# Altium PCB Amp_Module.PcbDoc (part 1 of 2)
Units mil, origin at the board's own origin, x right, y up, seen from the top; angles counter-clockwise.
Board outline 3270 x 1420 mil, 4 copper layers (Top Layer, InternalPlane1, InternalPlane2, Bottom Layer), stack 58.358 mil thick; 81 components, 51 nets, 288 pads, 46 vias.
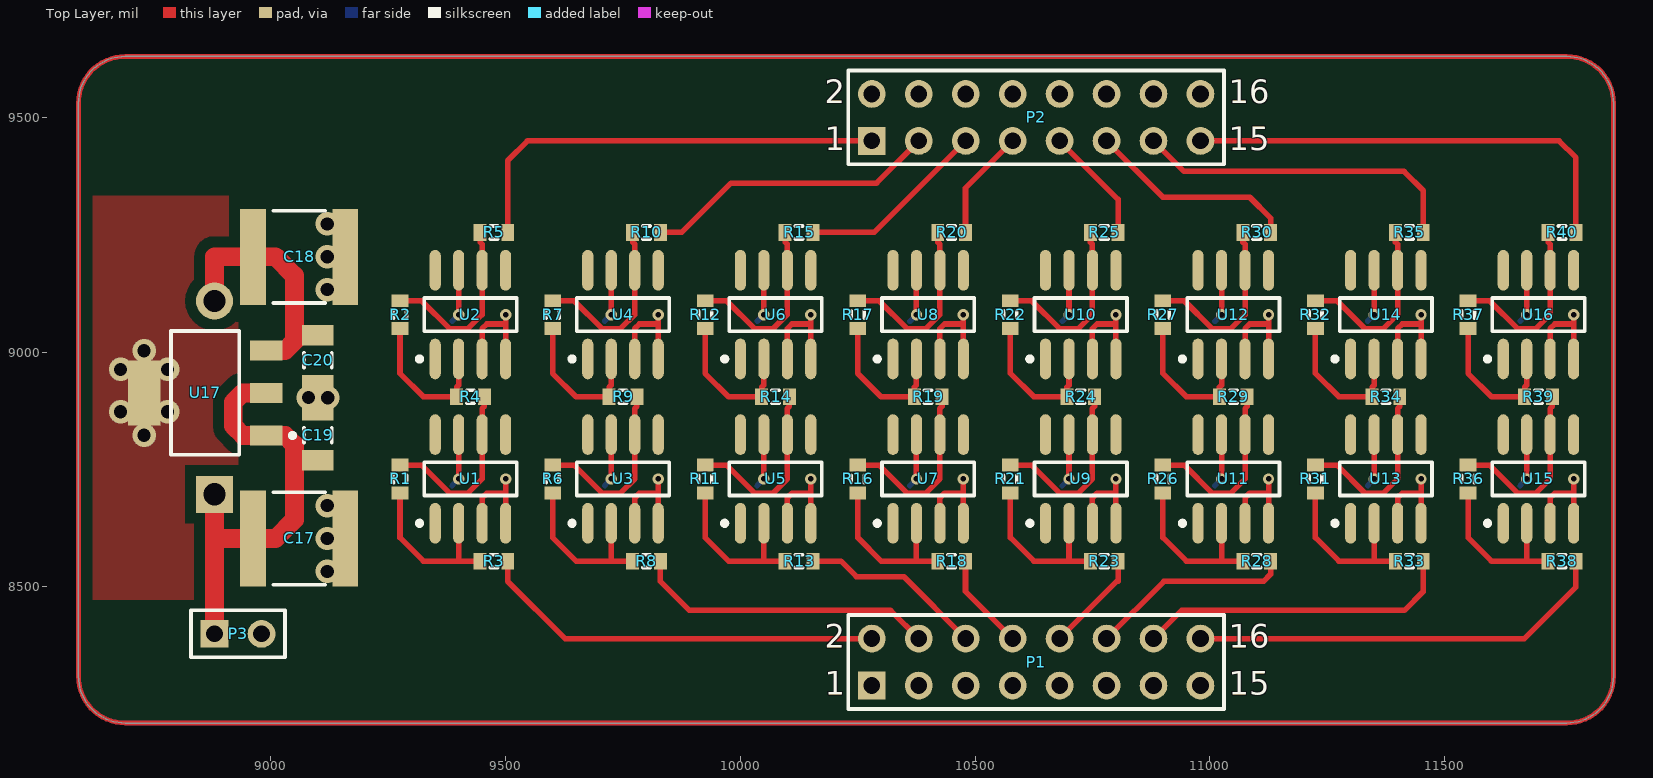
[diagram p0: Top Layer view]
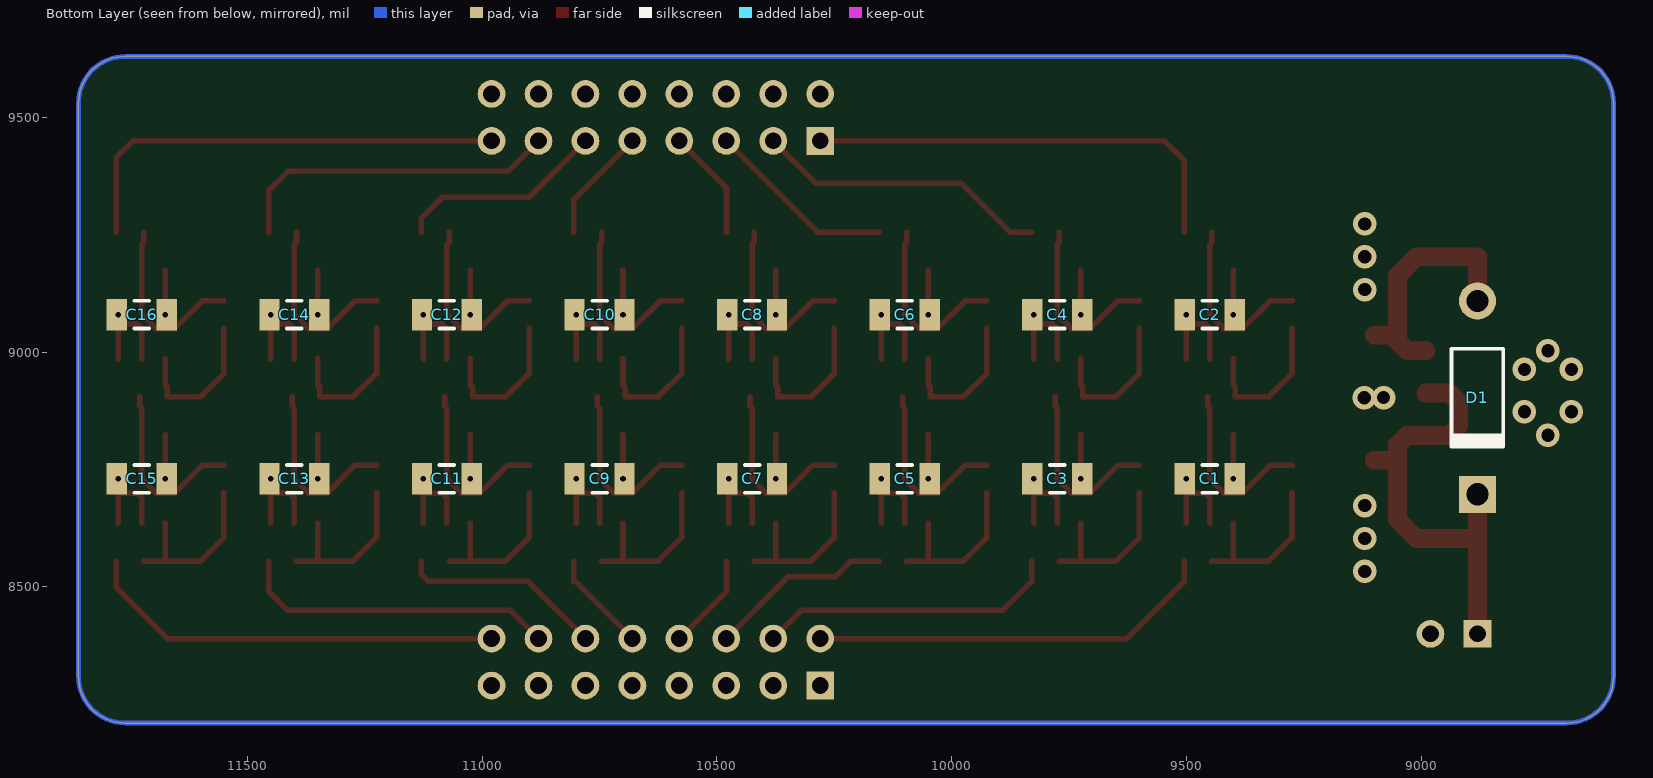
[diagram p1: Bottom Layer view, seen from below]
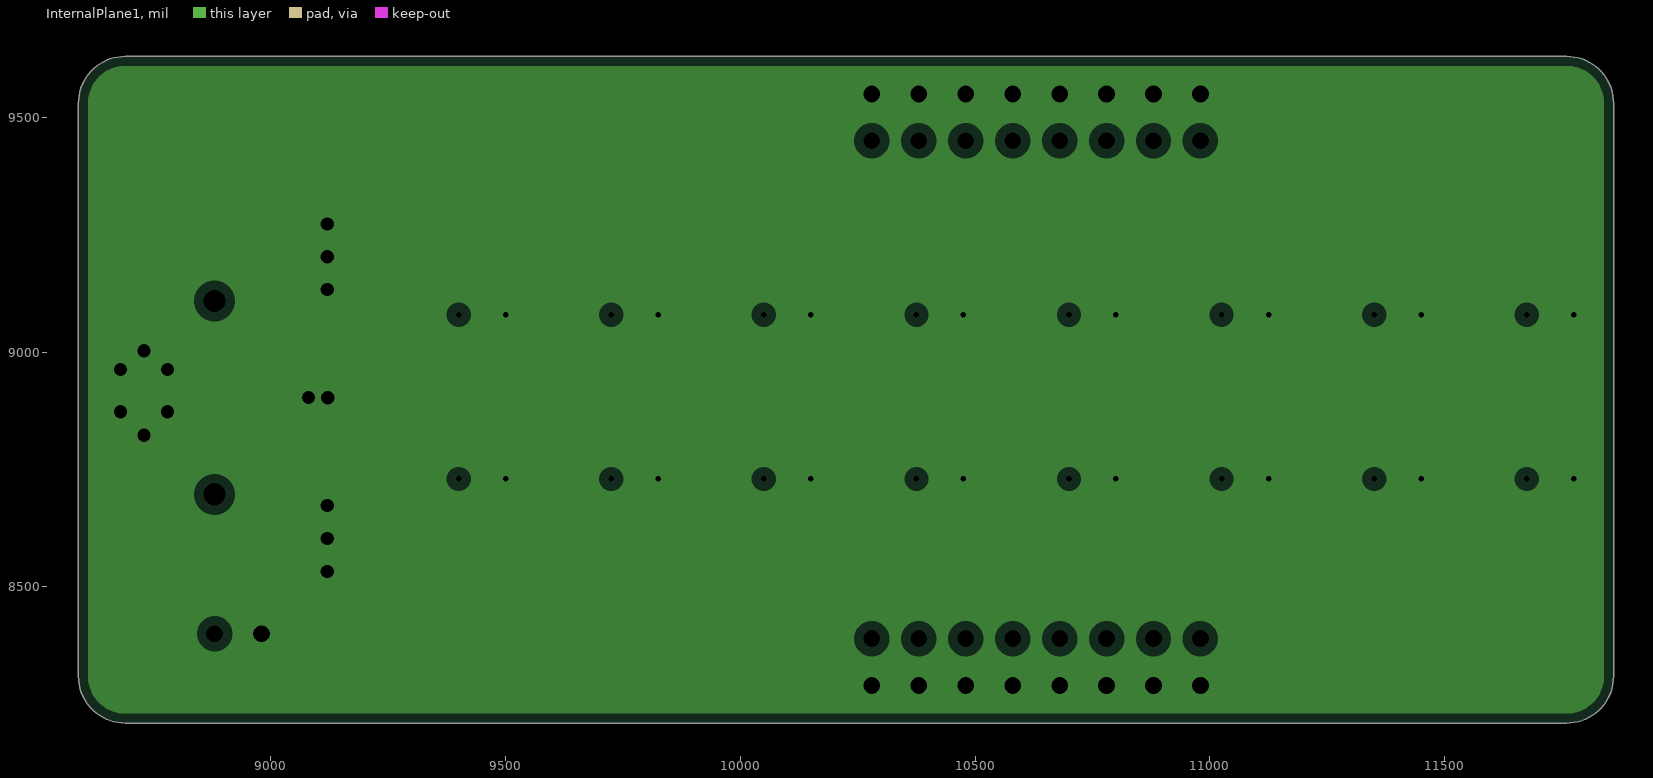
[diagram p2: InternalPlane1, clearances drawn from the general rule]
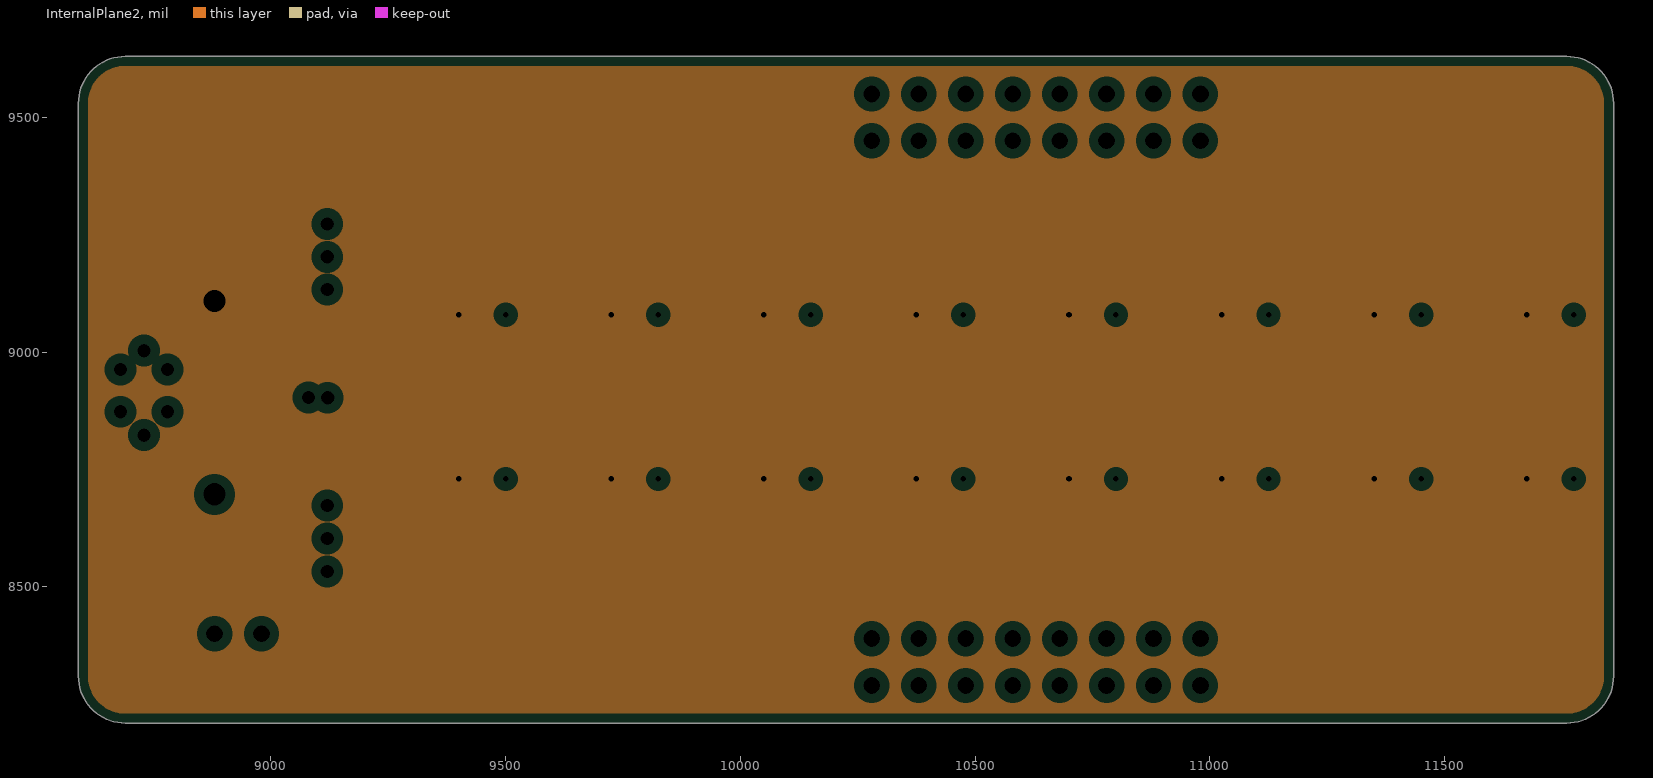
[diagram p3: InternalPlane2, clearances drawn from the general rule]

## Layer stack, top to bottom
Top Layer: signal copper 1.4
Dielectric: core 12.5984, FR-4, Dk 4.8
InternalPlane1: plane copper 1.4, net GND
Dielectric: prepreg 27.5591, FR-4, Dk 4.8
InternalPlane2: plane copper 1.4, net 3V3
Dielectric: core 12.6, FR-4, Dk 4.8
Bottom Layer: signal copper 1.4

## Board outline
8590,8310 8590,9530 cw(c8690,9530) 8690,9630 11760,9630 cw(c11760,9530) 11860,9530 11860,8310 cw(c11760,8310) 11760,8210 8690,8210 cw(c8690,8310)

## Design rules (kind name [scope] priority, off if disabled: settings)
Clearance Clearance_2 [InNamedPolygon('GND_VREG')] p1: gap=23.62
Clearance Clearance_1 [InNamedPolygon('Bottom Layer-No Net')] p2: gap=23.62
Clearance [All] p3: gap=7.87
ComponentClearance ComponentClearance_1 [InComponent('C19') OR InComponent('C20') OR InComponent('U17')] p1: gap=0 collisioncheckmode=3 verticalgap=0 showdistances=FALSE
ComponentClearance [All] p2: gap=10 collisioncheckmode=3 verticalgap=3.94 showdistances=TRUE
FabricationTestPointUsage TestPointUsage [All] p1: valid=0 allowmultiple=FALSE
FabricationTestpoint Testpoint [All] p1: side=3 testpointundercomponent=TRUE minsize=40 maxsize=100 preferedsize=60 minholesize=0 maxholesize=40 preferedholesize=32 testpointgrid=1 allowsidetop=TRUE allowsidebottom=TRUE usegrid=TRUE gridtolerance=0.01
MinimumSolderMaskSliver [All] p1 off: minsoldermaskwidth=10
PlaneClearance [All] p1: clearance=20
PlaneConnect [All] p1: planeconnectstyle=Relief reliefexpansion=20 reliefentries=4 reliefconductorwidth=10 reliefairgap=10
PolygonConnect [All] p1: connectstyle=Direct reliefconductorwidth=10 reliefentries=4 polygonreliefangle="90 Angle"
RoomDefinition U_TPS75501_3V3 [InComponentClass('U_TPS75501_3V3')] p1: confinementstyle=ConfineIn formatcopy=TRUE lockcomponents=FALSE outline 8610.11,9343.15 8610.11,8463.15 9218.87,8463.15 9218.87,9343.15
RoomDefinition U_Amplifier_GenericGain8 [InComponentClass('U_Amplifier_GenericGain8')] p2: confinementstyle=ConfineIn formatcopy=TRUE lockcomponents=FALSE outline 11825,8505 11825,9305 11500,9305 11500,8505
RoomDefinition U_Amplifier_GenericGain7 [InComponentClass('U_Amplifier_GenericGain7')] p3: confinementstyle=ConfineIn formatcopy=TRUE lockcomponents=FALSE outline 11500,8505 11500,9305 11175,9305 11175,8505
RoomDefinition U_Amplifier_GenericGain6 [InComponentClass('U_Amplifier_GenericGain6')] p4: confinementstyle=ConfineIn formatcopy=TRUE lockcomponents=FALSE outline 11175,8505 11175,9305 10850,9305 10850,8505
RoomDefinition U_Amplifier_GenericGain5 [InComponentClass('U_Amplifier_GenericGain5')] p5: confinementstyle=ConfineIn formatcopy=TRUE lockcomponents=FALSE outline 10850,8505 10850,9305 10525,9305 10525,8505
RoomDefinition U_Amplifier_GenericGain4 [InComponentClass('U_Amplifier_GenericGain4')] p6: confinementstyle=ConfineIn formatcopy=TRUE lockcomponents=FALSE outline 10525,8505 10525,9305 10200,9305 10200,8505
RoomDefinition U_Amplifier_GenericGain3 [InComponentClass('U_Amplifier_GenericGain3')] p7: confinementstyle=ConfineIn formatcopy=TRUE lockcomponents=FALSE outline 10200,8505 10200,9305 9875,9305 9875,8505
RoomDefinition U_Amplifier_GenericGain2 [InComponentClass('U_Amplifier_GenericGain2')] p8: confinementstyle=ConfineIn formatcopy=TRUE lockcomponents=FALSE outline 9875,8505 9875,9305 9550,9305 9550,8505
RoomDefinition U_Amplifier_GenericGain1 [InComponentClass('U_Amplifier_GenericGain1')] p9: confinementstyle=ConfineIn formatcopy=TRUE lockcomponents=FALSE outline 9550,8505 9550,9305 9225,9305 9225,8505
RoutingVias [All] p1: holewidth=15.75 width=23.62 viastyle="Through Hole" minholewidth=11.81 minwidth=15.75 maxholewidth=47.24 maxwidth=62.99
SilkToSilkClearance [All] p1 off: silktosilkclearance=10
SilkscreenOverComponentPads [All] p1 off: minsilkscreentomaskgap=10
SolderMaskExpansion [All] p1: expansion=4
Width [All] p1: maxlimit=118.11 minlimit=3.94 preferedwidth=11.81
20 further rules are at their usual default settings.

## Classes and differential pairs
net class PWRNET: 3V3
net class AMP_OUT[1..8]: AMP_OUT1 AMP_OUT2 AMP_OUT3 AMP_OUT4 AMP_OUT5 AMP_OUT6 AMP_OUT7 AMP_OUT8
net class AMP_IN[1..8]: AMP_IN1 AMP_IN2 AMP_IN3 AMP_IN4 AMP_IN5 AMP_IN6 AMP_IN7 AMP_IN8
component class U_TPS75501_3V3: C17 C18 C19 C20 D1 U17
component class U_Amplifier_GenericGain8: C15 C16 R36 R37 R38 R39 R40 U15 U16
component class U_Amplifier_GenericGain7: C13 C14 R31 R32 R33 R34 R35 U13 U14
component class U_Amplifier_GenericGain6: C11 C12 R26 R27 R28 R29 R30 U11 U12
component class U_Amplifier_GenericGain5: C9 C10 R21 R22 R23 R24 R25 U9 U10
component class U_Amplifier_GenericGain4: C7 C8 R16 R17 R18 R19 R20 U7 U8
component class U_Amplifier_GenericGain3: C5 C6 R11 R12 R13 R14 R15 U5 U6
component class U_Amplifier_GenericGain2: C3 C4 R6 R7 R8 R9 R10 U3 U4
component class U_Amplifier_GenericGain1: C1 C2 R1 R2 R3 R4 R5 U1 U2
component class Hierarchy_Top: P1 P2 P3
channel class Amplifier_GenericGain: U_Amplifier_GenericGain1 U_Amplifier_GenericGain2 U_Amplifier_GenericGain3 U_Amplifier_GenericGain4 U_Amplifier_GenericGain5 U_Amplifier_GenericGain6 U_Amplifier_GenericGain7 U_Amplifier_GenericGain8

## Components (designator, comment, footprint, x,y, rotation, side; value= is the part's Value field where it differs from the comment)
C1 "Cap Semi" C1206 9450,8730 r0 bottom
C2 "Cap Semi" C1206 9450,9080 r0 bottom
C3 "Cap Semi" C1206 9775,8730 r0 bottom (schematic designator C1)
C4 "Cap Semi" C1206 9775,9080 r0 bottom (schematic designator C2)
C5 "Cap Semi" C1206 10100,8730 r0 bottom (schematic designator C1)
C6 "Cap Semi" C1206 10100,9080 r0 bottom (schematic designator C2)
C7 "Cap Semi" C1206 10425,8730 r0 bottom (schematic designator C1)
C8 "Cap Semi" C1206 10425,9080 r0 bottom (schematic designator C2)
C9 "Cap Semi" C1206 10750,8730 r0 bottom (schematic designator C1)
C10 "Cap Semi" C1206 10750,9080 r0 bottom (schematic designator C2)
C11 "Cap Semi" C1206 11075,8730 r0 bottom (schematic designator C1)
C12 "Cap Semi" C1206 11075,9080 r0 bottom (schematic designator C2)
C13 "Cap Semi" C1206 11400,8730 r0 bottom (schematic designator C1)
C14 "Cap Semi" C1206 11400,9080 r0 bottom (schematic designator C2)
C15 "Cap Semi" C1206 11725,8730 r0 bottom (schematic designator C1)
C16 "Cap Semi" C1206 11725,9080 r0 bottom (schematic designator C2)
C17 "Cap Pol3" 2220 9060,8603.15 r0 top (schematic designator C1)
C18 "Cap Pol3" 2220 9060,9203.15 r0 top (schematic designator C2)
C19 "Cap Semi" C1206 9100,8823.15 r90 top (schematic designator C3)
C20 "Cap Semi" C1206 9100,8983.15 r270 top (schematic designator C4)
D1 "Diode 1N4001" DO-41 8880,8903.15 r270 bottom
P1 "Header 8X2" HDR2X8 10280,8290 r0 top (schematic designator P2)
P2 "Header 8X2" HDR2X8 10280,9450 r0 top (schematic designator P3)
P3 "Header 2" HDR1X2 8880,8400 r0 top (schematic designator P1)
R1 "Res3" J1-0603 9275,8730 r90 top
R2 "Res3" J1-0603 9275,9080 r90 top
R3 "Res3" J1-0603 9475,8555 r180 top
R4 "Res3" J1-0603 9425,8905 r180 top
R5 "Res3" J1-0603 9475,9255 r0 top
R6 "Res3" J1-0603 9600,8730 r90 top (schematic designator R1)
R7 "Res3" J1-0603 9600,9080 r90 top (schematic designator R2)
R8 "Res3" J1-0603 9800,8555 r180 top (schematic designator R3)
R9 "Res3" J1-0603 9750,8905 r180 top (schematic designator R4)
R10 "Res3" J1-0603 9800,9255 r0 top (schematic designator R5)
R11 "Res3" J1-0603 9925,8730 r90 top (schematic designator R1)
R12 "Res3" J1-0603 9925,9080 r90 top (schematic designator R2)
R13 "Res3" J1-0603 10125,8555 r180 top (schematic designator R3)
R14 "Res3" J1-0603 10075,8905 r180 top (schematic designator R4)
R15 "Res3" J1-0603 10125,9255 r0 top (schematic designator R5)
R16 "Res3" J1-0603 10250,8730 r90 top (schematic designator R1)
R17 "Res3" J1-0603 10250,9080 r90 top (schematic designator R2)
R18 "Res3" J1-0603 10450,8555 r180 top (schematic designator R3)
R19 "Res3" J1-0603 10400,8905 r180 top (schematic designator R4)
R20 "Res3" J1-0603 10450,9255 r0 top (schematic designator R5)
R21 "Res3" J1-0603 10575,8730 r90 top (schematic designator R1)
R22 "Res3" J1-0603 10575,9080 r90 top (schematic designator R2)
R23 "Res3" J1-0603 10775,8555 r180 top (schematic designator R3)
R24 "Res3" J1-0603 10725,8905 r180 top (schematic designator R4)
R25 "Res3" J1-0603 10775,9255 r0 top (schematic designator R5)
R26 "Res3" J1-0603 10900,8730 r90 top (schematic designator R1)
R27 "Res3" J1-0603 10900,9080 r90 top (schematic designator R2)
R28 "Res3" J1-0603 11100,8555 r180 top (schematic designator R3)
R29 "Res3" J1-0603 11050,8905 r180 top (schematic designator R4)
R30 "Res3" J1-0603 11100,9255 r0 top (schematic designator R5)
R31 "Res3" J1-0603 11225,8730 r90 top (schematic designator R1)
R32 "Res3" J1-0603 11225,9080 r90 top (schematic designator R2)
R33 "Res3" J1-0603 11425,8555 r180 top (schematic designator R3)
R34 "Res3" J1-0603 11375,8905 r180 top (schematic designator R4)
R35 "Res3" J1-0603 11425,9255 r0 top (schematic designator R5)
R36 "Res3" J1-0603 11550,8730 r90 top (schematic designator R1)
R37 "Res3" J1-0603 11550,9080 r90 top (schematic designator R2)
R38 "Res3" J1-0603 11750,8555 r180 top (schematic designator R3)
R39 "Res3" J1-0603 11700,8905 r180 top (schematic designator R4)
R40 "Res3" J1-0603 11750,9255 r0 top (schematic designator R5)
U1 "OP77GS" SO-8_N 9425,8730 r90 top
U2 "OP77GS" SO-8_N 9425,9080 r90 top
U3 "OP77GS" SO-8_N 9750,8730 r90 top (schematic designator U1)
U4 "OP77GS" SO-8_N 9750,9080 r90 top (schematic designator U2)
U5 "OP77GS" SO-8_N 10075,8730 r90 top (schematic designator U1)
U6 "OP77GS" SO-8_N 10075,9080 r90 top (schematic designator U2)
U7 "OP77GS" SO-8_N 10400,8730 r90 top (schematic designator U1)
U8 "OP77GS" SO-8_N 10400,9080 r90 top (schematic designator U2)
U9 "OP77GS" SO-8_N 10725,8730 r90 top (schematic designator U1)
U10 "OP77GS" SO-8_N 10725,9080 r90 top (schematic designator U2)
U11 "OP77GS" SO-8_N 11050,8730 r90 top (schematic designator U1)
U12 "OP77GS" SO-8_N 11050,9080 r90 top (schematic designator U2)
U13 "OP77GS" SO-8_N 11375,8730 r90 top (schematic designator U1)
U14 "OP77GS" SO-8_N 11375,9080 r90 top (schematic designator U2)
U15 "OP77GS" SO-8_N 11700,8730 r90 top (schematic designator U1)
U16 "OP77GS" SO-8_N 11700,9080 r90 top (schematic designator U2)
U17 "MC33375ST-3.3T3" 318E-04 8860,8913.15 r90 top (schematic designator U1)

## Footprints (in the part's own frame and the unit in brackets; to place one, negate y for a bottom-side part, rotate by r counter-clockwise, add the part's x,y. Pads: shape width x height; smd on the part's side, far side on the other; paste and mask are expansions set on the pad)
318E-04 [mm] "SOT-223/SC-73; 4 Leads; Body 6.7 x 7.3 mm, inc. leads (LxW max)"
  rect 1.1x1.75 smd: 1(-2.3,-3.3) 2(0,-3.3) 3(2.3,-3.3)
  rect 3.5x1.75 smd: 4(0,3.3)
  silkscreen extent -3.35,-4.85 3.35,1.85
2220 [mm] "Chip Capacitor, Body 5.7x5.0mm, IPC High Density"
  rect 1.4x5.2 smd: 1(-2.5,0) 2(2.5,0)
  silkscreen extent -1.4,-2.5 1.4,2.5, body extent -2.95,-2.63 2.95,2.63, height 1.4
C1206 [mm] "Chip Capacitor, Body 3.2x1.6mm, IPC High Density"
  rect 1.1x1.7 smd: 1(-1.35,0) 2(1.35,0)
  silkscreen extent -0.4,-0.75 0.4,0.75, body extent -1.7,-0.9 1.7,0.9, height 1.3
DO-41 [mm] "Diode, Axial; Body 5.2 x 2.7 mm (LxDia. max), Lead Dia. 0.86 mm (max)"
  round 2 hole 1.2: 1(-5.23,0)
  rect 2x2 hole 1.2: 2(5.23,0)
  silkscreen extent -2.65,-1.4 2.74,1.4
HDR1X2 [mm] "Connector; Header; 2 Position"
  rect 1.5x1.5 hole 0.9: 1(0,0)
  round 1.5 hole 0.9: 2(2.54,0)
  silkscreen extent -1.27,-1.27 3.81,1.27
HDR2X8 [mm] "Connector; Header; 8x2 Position"
  rect 1.5x1.5 hole 0.9: 1(0,0)
  round 1.5 hole 0.9: 2(0,2.54) 3(2.54,0) 4(2.54,2.54) 5(5.08,0) 6(5.08,2.54) 7(7.62,0) 8(7.62,2.54) 9(10.16,0) 10(10.16,2.54) 11(12.7,0) 12(12.7,2.54) 13(15.24,0) 14(15.24,2.54) 15(17.78,0) 16(17.78,2.54)
  silkscreen extent -1.27,-1.27 19.05,3.81
J1-0603 [mm] "Chip Resistor, Body 1.6x0.8mm, IPC High Density"
  rect 0.7x0.9 smd: 1(-0.75,0) 2(0.75,0)
  silkscreen extent -0.2,-0.35 0.2,0.35, body extent -0.85,-0.48 0.85,0.48, height 0.9
SO-8_N [mm] "SOIC, 8-Leads, Body 4.9x3.9mm, Pitch 1.27mm, IPC Medium Density"
  oval 2.2x0.6 smd: 1(-2.4,1.905) 2(-2.4,0.635) 3(-2.4,-0.635) 4(-2.4,-1.905) 5(2.4,-1.905) 6(2.4,-0.635) 7(2.4,0.635) 8(2.4,1.905)
  silkscreen extent -2.52,-2.5 0.9,2.88, body extent -1.95,-2.45 1.95,2.45, height 1.75

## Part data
C1 C2 C3 C4 C5 C6 C7 C8 C9 C10 C11 C12 C13 C14 C15 C16 C19 C20: "Capacitor (Semiconductor SIM Model)"
C17 C18: "Polarized Capacitor (Surface Mount)"
D1: "1 Amp General Purpose Rectifier"
P1 P2: "Header, 8-Pin, Dual row"
P3: "Header, 2-Pin"
R1 R2 R3 R4 R5 R6 R7 R8 R9 R10 R11 R12 R13 R14 R15 R16 R17 R18 R19 R20 R21 R22 R23 R24 R25 R26 R27 R28 R29 R30 R31 R32 R33 R34 R35 R36 R37 R38 R39 R40: "Resistor"
U1 U2 U3 U4 U5 U6 U7 U8 U9 U10 U11 U12 U13 U14 U15 U16: "Ultra-Low Offset Voltage Operational Amplifier"
U17: "Low Dropout 300mA Voltage Regulator with ON/OFF Control"

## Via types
v1: diameter 24, hole 11.81, Top Layer to Bottom Layer, 32 vias
v2: diameter 50, hole 28, Top Layer to Bottom Layer, 14 vias

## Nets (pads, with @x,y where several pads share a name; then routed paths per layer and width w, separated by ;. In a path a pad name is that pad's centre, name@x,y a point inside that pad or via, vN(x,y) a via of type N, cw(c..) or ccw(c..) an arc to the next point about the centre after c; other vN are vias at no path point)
3V3: C1.1 C2.1 C3.1 C4.1 C5.1 C6.1 C7.1 C8.1 C9.1 C10.1 C11.1 C12.1 C13.1 C14.1 C15.1 C16.1 C18.1 C20.1 D1.1 U1.7 U2.7 U3.7 U4.7 U5.7 U6.7 U7.7 U8.7 U9.7 U10.7 U11.7 U12.7 U13.7 U14.7 U15.7 U16.7 U17.3 | length 2695
  Top Layer w11.81: v1(9400,8730) U1.7@9400,8824.49 ; v1(9400,9080) U2.7@9400,9174.49 ; v1(9725,8730) U3.7@9725,8824.49 ; v1(9725,9080) U4.7@9725,9174.49 ; v1(10050,8730) U5.7@10050,8824.49 ; v1(10050,9080) U6.7@10050,9174.49 ; v1(10375,8730) U7.7@10375,8824.49 ; v1(10375,9080) U8.7@10375,9174.49 ; v1(10700,8730) U9.7@10700,8824.49 ; v1(10700,9080) U10.7@10700,9174.49 ; v1(11025,8730) U11.7@11025,8824.49 ; v1(11025,9080) U12.7@11025,9174.49 ; v1(11350,8730) U13.7@11350,8824.49 ; v1(11350,9080) U14.7@11350,9174.49 ; v1(11675,8730) U15.7@11675,8824.49 ; v1(11675,9080) U16.7@11675,9174.49
  Top Layer w40: D1.1@8880,9109.06 8880,9203.15 C18.1@8961.57,9203.15 9010,9203.15 9050,9163.15 9050,9023.15 ; U17.3@8989.92,9003.7 8990.47,9003.15 9030,9003.15 9050,9023.15 ; C20.1@9100,9036.3 9063.15,9036.3 9050,9023.15
  Bottom Layer w11.81: C1.1@9385.93,8715.93 v1(9400,8730) C1.1@9400,8750 ; C2.1@9385.93,9065.93 v1(9400,9080) C2.1@9400,9100 ; C3.1@9710.93,8715.93 v1(9725,8730) C3.1@9725,8750 ; C4.1@9710.93,9065.93 v1(9725,9080) C4.1@9725,9100 ; C5.1@10035.93,8715.93 v1(10050,8730) C5.1@10050,8750 ; C6.1@10035.93,9065.93 v1(10050,9080) C6.1@10050,9100 ; C7.1@10360.93,8715.93 v1(10375,8730) C7.1@10375,8750 ; C8.1@10360.93,9065.93 v1(10375,9080) C8.1@10375,9100 ; C9.1@10685.93,8715.93 v1(10700,8730) C9.1@10700,8750 ; C10.1@10685.93,9065.93 v1(10700,9080) C10.1@10700,9100 ; C11.1@11010.93,8715.93 v1(11025,8730) C11.1@11025,8750 ; C12.1@11010.93,9065.93 v1(11025,9080) C12.1@11025,9100 ; C13.1@11335.93,8715.93 v1(11350,8730) C13.1@11350,8750 ; C14.1@11335.93,9065.93 v1(11350,9080) C14.1@11350,9100 ; C15.1@11660.93,8715.93 v1(11675,8730) C15.1@11675,8750 ; C16.1@11660.93,9065.93 v1(11675,9080) C16.1@11675,9100
AMP_IN1: P1.2 R3.1 | length 869
  Top Layer w11.81: R3.1@9504.53,8555 9504.53,8512 9626.53,8390 P1.2@10280,8390
AMP_IN2: P1.4 R8.1 | length 644
  Top Layer w11.81: R8.1@9829.53,8555 9829.53,8512 9891.36,8450.17 10319.83,8450.17 P1.4@10380,8390
AMP_IN3: P1.6 R13.1 | length 393.8
  Top Layer w11.81: R13.1@10154.53,8555 10214,8555 10247,8522 10348,8522 P1.6@10480,8390
AMP_IN4: P1.8 R18.1 | length 206.6
  Top Layer w11.81: R18.1@10479.53,8555 10479.53,8490.47 P1.8@10580,8390
AMP_IN5: P1.10 R23.1 | length 219.1
  Top Layer w11.81: P1.10@10680,8390 10804.53,8514.53 ; 10804.53,8512 10804.53,8514.53 ; R23.1@10804.53,8555 10804.53,8514.53
AMP_IN6: P1.12 R28.1 | length 434.3
  Top Layer w11.81: P1.12@10780,8390 10902,8512 11114.53,8512 11129.53,8527 R28.1@11129.53,8555
AMP_IN7: P1.14 R33.1 | length 680.9
  Top Layer w11.81: P1.14@10880,8390 10940,8450 11414.53,8450 11454.53,8490 R33.1@11454.53,8555
AMP_IN8: P1.16 R38.1 | length 900.4
  Top Layer w11.81: P1.16@10980,8390 11670,8390 11779.53,8499.53 R38.1@11779.53,8555
AMP_OUT1: P2.1 R5.2 | length 945.9
  Top Layer w11.81: R5.2@9504.53,9255 9504.53,9408 9546.53,9450 P2.1@10280,9450
AMP_OUT2: P2.3 R10.2 | length 631.2
  Top Layer w11.81: R10.2@9829.53,9255 9875,9255 9980,9360 10290,9360 P2.3@10380,9450
AMP_OUT3: P2.5 R15.2 | length 406.2
  Top Layer w11.81: R15.2@10154.53,9255 10285,9255 P2.5@10480,9450
AMP_OUT4: P2.7 R20.2 | length 236.6
  Top Layer w11.81: R20.2@10479.53,9255 10479.53,9349.53 P2.7@10580,9450
AMP_OUT5: P2.9 R25.2 | length 246.6
  Top Layer w11.81: P2.9@10680,9450 10804.53,9325.47 R25.2@10804.53,9255
AMP_OUT6: P2.11 R30.2 | length 448.1
  Top Layer w11.81: P2.11@10780,9450 10900,9330 11085,9330 11129.53,9285.47 R30.2@11129.53,9255
AMP_OUT7: P2.13 R35.2 | length 707.4
  Top Layer w11.81: P2.13@10880,9450 10945,9385 11413.53,9385 11454.53,9344 R35.2@11454.53,9255
AMP_OUT8: P2.15 R40.2 | length 973.7
  Top Layer w11.81: P2.15@10980,9450 11744,9450 11779.53,9414.47 R40.2@11779.53,9255
GND: C1.2 C2.2 C3.2 C4.2 C5.2 C6.2 C7.2 C8.2 C9.2 C10.2 C11.2 C12.2 C13.2 C14.2 C15.2 C16.2 C17.2 C18.2 C19.2 C20.2 P1.1 P1.3 P1.5 P1.7 P1.9 P1.11 P1.13 P1.15 P2.2 P2.4 P2.6 P2.8 P2.10 P2.12 P2.14 P2.16 P3.2 U1.3 U1.4 U2.3 U2.4 U3.3 U3.4 U4.3 U4.4 U5.3 U5.4 U6.3 U6.4 U7.3 U7.4 U8.3 U8.4 U9.3 U9.4 U10.3 U10.4 U11.3 U11.4 U12.3 U12.4 U13.3 U13.4 U14.3 U14.4 U15.3 U15.4 U16.3 U16.4 U17.4 | length 3329.9
  Top Layer w11.81: U1.3@9450,8635.51 9450,8690 9460,8700 9500,8700 ; U2.3@9450,8985.51 9450,9050 9460,9060 9500,9060 ; U1.4@9500,8635.51 v1(9500,8730) ; U2.4@9500,8985.51 v1(9500,9080) ; U3.3@9775,8635.51 9775,8690 9785,8700 9825,8700 ; U4.3@9775,8985.51 9775,9050 9785,9060 9825,9060 ; U3.4@9825,8635.51 v1(9825,8730) ; U4.4@9825,8985.51 v1(9825,9080) ; U5.3@10100,8635.51 10100,8690 10110,8700 10150,8700 ; U6.3@10100,8985.51 10100,9050 10110,9060 10150,9060 ; U5.4@10150,8635.51 v1(10150,8730) ; U6.4@10150,8985.51 v1(10150,9080) ; U7.3@10425,8635.51 10425,8690 10435,8700 10475,8700 ; U8.3@10425,8985.51 10425,9050 10435,9060 10475,9060 ; U7.4@10475,8635.51 v1(10475,8730) ; U8.4@10475,8985.51 v1(10475,9080) ; U9.3@10750,8635.51 10750,8690 10760,8700 10800,8700 ; U10.3@10750,8985.51 10750,9050 10760,9060 10800,9060 ; U9.4@10800,8635.51 v1(10800,8730) ; U10.4@10800,8985.51 v1(10800,9080) ; U11.3@11075,8635.51 11075,8690 11085,8700 11125,8700 ; U12.3@11075,8985.51 11075,9050 11085,9060 11125,9060 ; U11.4@11125,8635.51 v1(11125,8730) ; U12.4@11125,8985.51 v1(11125,9080) ; U13.3@11400,8635.51 11400,8690 11410,8700 11450,8700 ; U14.3@11400,8985.51 11400,9050 11410,9060 11450,9060 ; U13.4@11450,8635.51 v1(11450,8730) ; U14.4@11450,8985.51 v1(11450,9080) ; U15.3@11725,8635.51 11725,8690 11735,8700 11775,8700 ; U16.3@11725,8985.51 11725,9050 11735,9060 11775,9060 ; U15.4@11775,8635.51 v1(11775,8730) ; U16.4@11775,8985.51 v1(11775,9080)
  other v2: 9120,8533.15 9120,8603.15 9120,8673.15 8730,8823.15 8680,8873.15 8780,8873.15 9080,8903.15 9121,8903 8680,8963.15 8780,8963.15 8730,9003.15 9120,9133.15 9120,9203.15 9120,9273.15
NetR1_1: R1.1 R3.2 U1.2 | length 367.2
  Top Layer w11.81: R1.1@9275,8700.47 9275,8605 9325,8555 9400,8555 ; U1.2@9400,8635.51 9400,8555 ; R3.2@9445.47,8555 9400,8555
NetR1_2: R1.2 R4.1 U1.6 | length 389
  Top Layer w11.81: R1.2@9275,8759.53 9320.47,8759.53 9380,8700 9420,8700 9450,8730 U1.6@9450,8824.49 9450,8880 9454.53,8884.53 R4.1@9454.53,8905
NetR2_1: R2.1 R4.2 U2.2 | length 319
  Top Layer w11.81: R2.1@9275,9050.47 9275,8955 9325,8905 R4.2@9395.47,8905 9395.47,8925.47 9400,8930 U2.2@9400,8985.51
NetR2_2: R2.2 R5.1 U2.6 | length 389
  Top Layer w11.81: R2.2@9275,9109.53 9320.47,9109.53 9380,9050 9420,9050 9450,9080 U2.6@9450,9174.49 9450,9230 9445.47,9234.53 R5.1@9445.47,9255
NetR6_1: R6.1 R8.2 U3.2 | length 367.2
  Top Layer w11.81: R6.1@9600,8700.47 9600,8605 9650,8555 9725,8555 ; U3.2@9725,8635.51 9725,8555 ; R8.2@9770.47,8555 9725,8555
NetR6_2: R6.2 R9.1 U3.6 | length 389
  Top Layer w11.81: R6.2@9600,8759.53 9645.47,8759.53 9705,8700 9745,8700 9775,8730 U3.6@9775,8824.49 9775,8880 9779.53,8884.53 R9.1@9779.53,8905
NetR7_1: R7.1 R9.2 U4.2 | length 319
  Top Layer w11.81: R7.1@9600,9050.47 9600,8955 9650,8905 R9.2@9720.47,8905 9720.47,8925.47 9725,8930 U4.2@9725,8985.51
NetR7_2: R7.2 R10.1 U4.6 | length 389
  Top Layer w11.81: R7.2@9600,9109.53 9645.47,9109.53 9705,9050 9745,9050 9775,9080 U4.6@9775,9174.49 9775,9230 9770.47,9234.53 R10.1@9770.47,9255
NetR11_1: R11.1 R13.2 U5.2 | length 367.2
  Top Layer w11.81: R11.1@9925,8700.47 9925,8605 9975,8555 10050,8555 ; U5.2@10050,8635.51 10050,8555 ; R13.2@10095.47,8555 10050,8555
NetR11_2: R11.2 R14.1 U5.6 | length 389
  Top Layer w11.81: R11.2@9925,8759.53 9970.47,8759.53 10030,8700 10070,8700 10100,8730 U5.6@10100,8824.49 10100,8880 10104.53,8884.53 R14.1@10104.53,8905
NetR12_1: R12.1 R14.2 U6.2 | length 319
  Top Layer w11.81: R12.1@9925,9050.47 9925,8955 9975,8905 R14.2@10045.47,8905 10045.47,8925.47 10050,8930 U6.2@10050,8985.51
NetR12_2: R12.2 R15.1 U6.6 | length 389
  Top Layer w11.81: R12.2@9925,9109.53 9970.47,9109.53 10030,9050 10070,9050 10100,9080 U6.6@10100,9174.49 10100,9230 10095.47,9234.53 R15.1@10095.47,9255
NetR16_1: R16.1 R18.2 U7.2 | length 367.2
  Top Layer w11.81: R16.1@10250,8700.47 10250,8605 10300,8555 10375,8555 ; U7.2@10375,8635.51 10375,8555 ; R18.2@10420.47,8555 10375,8555
NetR16_2: R16.2 R19.1 U7.6 | length 389
  Top Layer w11.81: R16.2@10250,8759.53 10295.47,8759.53 10355,8700 10395,8700 10425,8730 U7.6@10425,8824.49 10425,8880 10429.53,8884.53 R19.1@10429.53,8905
NetR17_1: R17.1 R19.2 U8.2 | length 319
  Top Layer w11.81: R17.1@10250,9050.47 10250,8955 10300,8905 R19.2@10370.47,8905 10370.47,8925.47 10375,8930 U8.2@10375,8985.51
NetR17_2: R17.2 R20.1 U8.6 | length 389
  Top Layer w11.81: R17.2@10250,9109.53 10295.47,9109.53 10355,9050 10395,9050 10425,9080 U8.6@10425,9174.49 10425,9230 10420.47,9234.53 R20.1@10420.47,9255
NetR21_1: R21.1 R23.2 U9.2 | length 367.2
  Top Layer w11.81: R21.1@10575,8700.47 10575,8605 10625,8555 10700,8555 ; U9.2@10700,8635.51 10700,8555 ; R23.2@10745.47,8555 10700,8555
NetR21_2: R21.2 R24.1 U9.6 | length 389
  Top Layer w11.81: R21.2@10575,8759.53 10620.47,8759.53 10680,8700 10720,8700 10750,8730 U9.6@10750,8824.49 10750,8880 10754.53,8884.53 R24.1@10754.53,8905
NetR22_1: R22.1 R24.2 U10.2 | length 319
  Top Layer w11.81: R22.1@10575,9050.47 10575,8955 10625,8905 R24.2@10695.47,8905 10695.47,8925.47 10700,8930 U10.2@10700,8985.51
NetR22_2: R22.2 R25.1 U10.6 | length 389
  Top Layer w11.81: R22.2@10575,9109.53 10620.47,9109.53 10680,9050 10720,9050 10750,9080 U10.6@10750,9174.49 10750,9230 10745.47,9234.53 R25.1@10745.47,9255
NetR26_1: R26.1 R28.2 U11.2 | length 367.2
  Top Layer w11.81: R26.1@10900,8700.47 10900,8605 10950,8555 11025,8555 ; U11.2@11025,8635.51 11025,8555 ; R28.2@11070.47,8555 11025,8555
NetR26_2: R26.2 R29.1 U11.6 | length 389
  Top Layer w11.81: R26.2@10900,8759.53 10945.47,8759.53 11005,8700 11045,8700 11075,8730 U11.6@11075,8824.49 11075,8880 11079.53,8884.53 R29.1@11079.53,8905
NetR27_1: R27.1 R29.2 U12.2 | length 319
  Top Layer w11.81: R27.1@10900,9050.47 10900,8955 10950,8905 R29.2@11020.47,8905 11020.47,8925.47 11025,8930 U12.2@11025,8985.51
NetR27_2: R27.2 R30.1 U12.6 | length 389
  Top Layer w11.81: R27.2@10900,9109.53 10945.47,9109.53 11005,9050 11045,9050 11075,9080 U12.6@11075,9174.49 11075,9230 11070.47,9234.53 R30.1@11070.47,9255
NetR31_1: R31.1 R33.2 U13.2 | length 367.2
  Top Layer w11.81: R31.1@11225,8700.47 11225,8605 11275,8555 11350,8555 ; U13.2@11350,8635.51 11350,8555 ; R33.2@11395.47,8555 11350,8555
NetR31_2: R31.2 R34.1 U13.6 | length 389
  Top Layer w11.81: R31.2@11225,8759.53 11270.47,8759.53 11330,8700 11370,8700 11400,8730 U13.6@11400,8824.49 11400,8880 11404.53,8884.53 R34.1@11404.53,8905
NetR32_1: R32.1 R34.2 U14.2 | length 319
  Top Layer w11.81: R32.1@11225,9050.47 11225,8955 11275,8905 R34.2@11345.47,8905 11345.47,8925.47 11350,8930 U14.2@11350,8985.51
NetR32_2: R32.2 R35.1 U14.6 | length 389
  Top Layer w11.81: R32.2@11225,9109.53 11270.47,9109.53 11330,9050 11370,9050 11400,9080 U14.6@11400,9174.49 11400,9230 11395.47,9234.53 R35.1@11395.47,9255
NetR36_1: R36.1 R38.2 U15.2 | length 367.2
  Top Layer w11.81: R36.1@11550,8700.47 11550,8605 11600,8555 11675,8555 ; U15.2@11675,8635.51 11675,8555 ; R38.2@11720.47,8555 11675,8555
NetR36_2: R36.2 R39.1 U15.6 | length 389
  Top Layer w11.81: R36.2@11550,8759.53 11595.47,8759.53 11655,8700 11695,8700 11725,8730 U15.6@11725,8824.49 11725,8880 11729.53,8884.53 R39.1@11729.53,8905
NetR37_1: R37.1 R39.2 U16.2 | length 319
  Top Layer w11.81: R37.1@11550,9050.47 11550,8955 11600,8905 R39.2@11670.47,8905 11670.47,8925.47 11675,8930 U16.2@11675,8985.51
NetR37_2: R37.2 R40.1 U16.6 | length 389
  Top Layer w11.81: R37.2@11550,9109.53 11595.47,9109.53 11655,9050 11695,9050 11725,9080 U16.6@11725,9174.49 11725,9230 11720.47,9234.53 R40.1@11720.47,9255
VCC: C17.1 C19.1 D1.2 P3.1 U17.1 U17.2 | length 969.9
  Top Layer w40: P3.1@8880,8400 8880,8603.15 ; D1.2@8880,8697.24 8880,8603.15 ; U17.2@8989.92,8913.15 8940,8913.15 8920,8893.15 8920,8843.15 8940.55,8822.6 U17.1@8989.92,8822.6 9030.55,8822.6 9050,8803.15 9050,8773.15 ; C19.1@9100,8770 9053.15,8770 9050,8773.15 ; 8880,8603.15 C17.1@8961.57,8603.15 9010,8603.15 9050,8643.15 9050,8773.15
pads on no net: U1.1 U1.5 U1.8 U2.1 U2.5 U2.8 U3.1 U3.5 U3.8 U4.1 U4.5 U4.8 U5.1 U5.5 U5.8 U6.1 U6.5 U6.8 U7.1 U7.5 U7.8 U8.1 U8.5 U8.8 U9.1 U9.5 U9.8 U10.1 U10.5 U10.8 U11.1 U11.5 U11.8 U12.1 U12.5 U12.8 U13.1 U13.5 U13.8 U14.1 U14.5 U14.8 U15.1 U15.5 U15.8 U16.1 U16.5 U16.8
copper on no net: | length 27164.8
  Top Layer w5: 13672.98,13929.05 13672.98,14024.05 14592.98,14024.05 14592.98,13929.05 13672.98,13929.05
  Top Layer w10: 6107.15,10595.13 6107.15,11057.18 6817.15,11057.18 6817.15,10595.13 6107.15,10595.13 ; 8590,8310 ccw(c8690,8310) 8690,8210 11760,8210 ccw(c11760,8310) 11860,8310 11860,9530 ccw(c11760,9530) 11760,9630 8690,9630 ccw(c8690,9530) 8590,9530 8590,8310
  Bottom Layer w5: 13672.98,13834.05 13672.98,13929.05 14592.98,13929.05 14592.98,13834.05 13672.98,13834.05
  Bottom Layer w10: 6107.15,10595.13 6107.15,11057.18 6817.15,11057.18 6817.15,10595.13 6107.15,10595.13 ; 8590,8310 ccw(c8690,8310) 8690,8210 11760,8210 ccw(c11760,8310) 11860,8310 11860,9530 ccw(c11760,9530) 11760,9630 8690,9630 ccw(c8690,9530) 8590,9530 8590,8310

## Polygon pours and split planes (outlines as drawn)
GND on Top Layer "GND_VREG" (solid, pour order 6): 8620,9333.15 8620,8473.15 8720,8473.15 8930,8473.15 8930,9333.15 8620,9333.15
no net on Top Solder "GND_VREG" (solid, pour order 6): 8620,9333.15 8620,8473.15 8720,8473.15 8930,8473.15 8930,9333.15 8620,9333.15
GND on InternalPlane1 (split plane): 11767.84,9609.61 11775.61,9608.46 11783.22,9606.55 11790.61,9603.91 11797.71,9600.55 11804.44,9596.51 11810.75,9591.84 11816.57,9586.57 11821.84,9580.75 11826.51,9574.44 11830.55,9567.71 11833.91,9560.61 11836.55,9553.22 11838.46,9545.61 11839.61,9537.84 11839.97,9530.63 11839.9,9530 11839.9,8310 11839.97,8309.37 11839.61,8302.16 11838.46,8294.39 11836.55,8286.78 11833.91,8279.39 11830.55,8272.29 11826.51,8265.56 11821.84,8259.25 11816.57,8253.43 11810.75,8248.16 11804.44,8243.49 11797.71,8239.45 11790.61,8236.09 11783.22,8233.45 11775.61,8231.54 11767.84,8230.39 11760.63,8230.03 11760,8230.1 8690,8230.1 8689.37,8230.03 8682.16,8230.39 8674.39,8231.54 8666.78,8233.45 8659.39,8236.09 8652.29,8239.45 8645.56,8243.49 8639.25,8248.16 8633.43,8253.43 8628.16,8259.25 8623.49,8265.56 8619.45,8272.29 8616.09,8279.39 8613.45,8286.78 8611.54,8294.39 8610.39,8302.16 8610.03,8309.37 8610.1,8310 8610.1,9530 8610.03,9530.63 8610.39,9537.84 8611.54,9545.61 8613.45,9553.22 8616.09,9560.61 8619.45,9567.71 8623.49,9574.44 8628.16,9580.75 8633.43,9586.57 8639.25,9591.84 8645.56,9596.51 8652.29,9600.55 8659.39,9603.91 8666.78,9606.55 8674.39,9608.46 8682.16,9609.61 8689.37,9609.97 8690,9609.9 11760,9609.9 11760.63,9609.97
3V3 on InternalPlane2 (split plane): 11767.84,9609.61 11775.61,9608.46 11783.22,9606.55 11790.61,9603.91 11797.71,9600.55 11804.44,9596.51 11810.75,9591.84 11816.57,9586.57 11821.84,9580.75 11826.51,9574.44 11830.55,9567.71 11833.91,9560.61 11836.55,9553.22 11838.46,9545.61 11839.61,9537.84 11839.97,9530.63 11839.9,9530 11839.9,8310 11839.97,8309.37 11839.61,8302.16 11838.46,8294.39 11836.55,8286.78 11833.91,8279.39 11830.55,8272.29 11826.51,8265.56 11821.84,8259.25 11816.57,8253.43 11810.75,8248.16 11804.44,8243.49 11797.71,8239.45 11790.61,8236.09 11783.22,8233.45 11775.61,8231.54 11767.84,8230.39 11760.63,8230.03 11760,8230.1 8690,8230.1 8689.37,8230.03 8682.16,8230.39 8674.39,8231.54 8666.78,8233.45 8659.39,8236.09 8652.29,8239.45 8645.56,8243.49 8639.25,8248.16 8633.43,8253.43 8628.16,8259.25 8623.49,8265.56 8619.45,8272.29 8616.09,8279.39 8613.45,8286.78 8611.54,8294.39 8610.39,8302.16 8610.03,8309.37 8610.1,8310 8610.1,9530 8610.03,9530.63 8610.39,9537.84 8611.54,9545.61 8613.45,9553.22 8616.09,9560.61 8619.45,9567.71 8623.49,9574.44 8628.16,9580.75 8633.43,9586.57 8639.25,9591.84 8645.56,9596.51 8652.29,9600.55 8659.39,9603.91 8666.78,9606.55 8674.39,9608.46 8682.16,9609.61 8689.37,9609.97 8690,9609.9 11760,9609.9 11760.63,9609.97

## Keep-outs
Keep-Out Layer:
  rectangle: 13672.98,12418.05 13862.98,12513.05
  lines w5: 13672.98,12418.05 13672.98,12513.05 14592.98,12513.05 14592.98,12418.05 13672.98,12418.05
  text "ROUTING KEEPOUT LAYER" at 13932.98,12445.05 h35

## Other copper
Top Layer:
  rectangle: 13672.98,13929.05 13862.98,14024.05
  text "TOP LAYER" at 13932.98,13956.05 h40
  text "LAYER" at 6337.58,10910.08 h60
  text "TOP" at 6310.02,10701.42 h120
Bottom Layer:
  rectangle: 13672.98,13834.05 13862.98,13929.05
  text "BOTTOM LAYER" at 13932.98,13861.05 h40
  text "LAYER" at 6337.58,10910.08 h60
  text "BOTTOM" at 6148.6,10705.35 h120
Multi-Layer:
  rectangle: 13672.98,13008.05 13862.98,13103.05
  lines w5: 13672.98,13008.05 13672.98,13103.05 14592.98,13103.05 14592.98,13008.05 13672.98,13008.05
  text "MULTILAYER" at 13932.98,13035.05 h40
  text "OF" at 22030.96,501.86 h80
  text "1" at 21835.88,501.31 h120
  text "1" at 22270.88,501.31 h120

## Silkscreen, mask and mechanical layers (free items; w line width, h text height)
Top Overlay:
  rectangle: 13672.98,14165.05 13862.98,14260.05
  lines w5: 13672.98,14165.05 14592.98,14165.05 14592.98,14260.05 13672.98,14260.05 13672.98,14165.05
  text "TOP OVERLAY" at 13932.98,14192.05 h40
Bottom Overlay:
  rectangle: 13672.98,13598.05 13862.98,13693.05
  lines w5: 13672.98,13598.05 14592.98,13598.05 14592.98,13693.05 13672.98,13693.05 13672.98,13598.05
  text "BOTTOM LEGEND" at 13932.98,13625.05 h40
Top Paste:
  rectangle: 13672.98,14283.05 13862.98,14378.05
  lines w5: 13672.98,14283.05 13672.98,14378.05 14592.98,14378.05 14592.98,14283.05 13672.98,14283.05
  text "TOP PASTE" at 13932.98,14310.05 h40
Bottom Paste:
  rectangle: 13672.98,13480.05 13862.98,13575.05
  lines w5: 13672.98,13480.05 13672.98,13575.05 14592.98,13575.05 14592.98,13480.05 13672.98,13480.05
  text "BOTTOM PASTE" at 13932.98,13507.05 h40
Top Solder:
  rectangle: 13672.98,14047.05 13862.98,14142.05
  lines w5: 13672.98,14047.05 14592.98,14047.05 14592.98,14142.05 13672.98,14142.05 13672.98,14047.05
  text "TOP SOLDER MASK" at 13932.98,14074.05 h40
Bottom Solder:
  rectangle: 13672.98,13716.05 13862.98,13811.05
  lines w5: 13672.98,13716.05 13672.98,13811.05 14592.98,13811.05 14592.98,13716.05 13672.98,13716.05
  text "BOTTOM SOLDER MASK" at 13932.98,13743.05 h40
Drill Guide:
  rectangle: 13672.98,13362.05 13862.98,13457.05
  lines w5: 13672.98,13362.05 14592.98,13362.05 14592.98,13457.05 13672.98,13457.05 13672.98,13362.05
  text "DRILL GUIDE (SLOTS)" at 13932.98,13389.05 h40
Mechanical 1:
  rectangle: 13672.98,13126.05 13862.98,13221.05
  rectangle: 13584.61,7299.25 15028.78,7361.12
  rectangle: 13584.61,7537.39 15028.78,7599.25
  lines w5: 13672.98,13126.05 14592.98,13126.05 14592.98,13221.05 13672.98,13221.05 13672.98,13126.05
  lines w10: 8590,8310 ccw(c8690,8310) 8690,8210 11760,8210 ccw(c11760,8310) 11860,8310 11860,9530 ccw(c11760,9530) 11760,9630 8690,9630 ccw(c8690,9530) 8590,9530 8590,8310 ; 13584.61,7299.25 13584.61,7599.25 15028.78,7599.25 15028.78,7299.25 13584.61,7299.25
  lines w12.01: 11879.01,8207.77 13584.63,7453.88
  text "BOARD OUTLINE" at 13932.98,13153.05 h40
  text "PCB BOARD OUTLINE" at 13745.65,7405.38 h80
Mechanical 3:
  rectangle: 13672.98,12890.05 13862.98,12985.05
  lines w5: 13672.98,12890.05 13672.98,12985.05 14592.98,12985.05 14592.98,12890.05 13672.98,12890.05
  lines w6: 6164.15,9211.91 6774.15,9211.91 6774.15,9461.91 6164.15,9461.91 6164.15,9211.91
  lines w8: 21948,2634 22873,2634
  lines w10: 6823,9270 8502.78,9062.51 ; 13762.98,14468.05 14532.98,14468.05 ; 6118.72,8557.91 6828.72,8557.91 6828.72,10001.91 6118.72,10001.91 6118.72,8557.91 ; 13572.98,12331.05 14702.98,12331.05 14702.98,14688.05 13572.98,14688.05 13572.98,12331.05
  lines w15: 6194.15,9801.91 6434.15,9801.91
  text "3 TRACK" at 17927.8,15741.57 h69
  text "24 VIA" at 18492.8,15741.57 h69
  text "3 SPACE" at 18992.8,15741.57 h69
  text "54.22mm" at 19763.55,15733.54 h69
  text "51.45mm" at 20507.64,15733.54 h69
  text "DS" at 19684,14937.36 h69
  text "X" at 19532.96,14935.36 h69
  text "LAYER USAGE" at 13762.98,14496.05 h80
  text "FEED THRU'" at 18968.18,14386.86 h69
  text "TENTED" at 19921,14386.86 h69
  text "X" at 19744,14384.86 h69
  text "X" at 18778.14,14383.36 h69
  text "UNIQUE DRILL" at 18968.18,14189.86 h69
  text "X" at 18778,14185.86 h69
  text "X" at 21405,14012.86 h69
  text "AS SHOWN" at 21555,14012.86 h69
  text "X" at 20335,13817.86 h69
  text "CAD" at 20492,13816.86 h69
  text "1" at 22563.37,13232.05 h69
  text "DT01.02" at 18014.96,13213.86 h69
  text "DEVELOPMENT TOOL 01.02" at 19634.96,13213.86 h69
  text "TECHNICAL DATA" at 13932.98,12917.05 h40
  text "NOTE" at 6190.15,9844.91 h70
  text "DRILL DRAWING" at 18167.43,9824.55 h69
  text "APERTURE TABLES\FILES ARE EMBEDDED" at 19776.43,9824.55 h69
  text "1" at 22562.3,9822.33 h69
  text "BOARDS HAVE" at 6190.15,9664.91 h50
  text "PLATED EDGES" at 6190.15,9564.91 h50
  text "TUC-722" at 22372.81,9540 h69
  text "X" at 22182.77,9537 h69
  text "MILL CUTOUTS" at 6224.15,9361.91 h50
  text "1.2mm" at 20000,9353 h69
  text "X" at 19809.96,9350 h69
  text "BEFORE PLATING" at 6200.15,9274.91 h50
  text "X" at 19101.57,9177.84 h68.9
  text "IN A/W ANSI IPC-6012 TYPE 2 CLASS 2" at 19291,9176.5 h69
  text "ALL" at 6392.59,9029.91 h50
  text "X" at 19100,9000.5 h69
  text "IN A/W ANSI IPC-6012 TYPE 2 CLASS 2" at 19291,8999.5 h69
  text "SIDES ARE" at 6274.88,8936.91 h50
  text "PLATED BY" at 6262.15,8846.91 h50
  text "DESIGN" at 6339.15,8756.91 h50
  text "35um (1oz)" at 20492,8643 h69
  text "X" at 20301.96,8640 h69
  text "35um (1oz)" at 20492,8466 h69
  text "X" at 20301.96,8463 h69
  text "35um (1oz)" at 20492,8290 h69
  text "X" at 20301.96,8287 h69
  text "AS SHOWN" at 21614,7917.5 h69
  text "X" at 21420,7916.5 h69
  text "X" at 19105,7622.5 h69
  text "COMPONENT SIDE" at 19291,7622.5 h69
  text "X" at 19105,7446.5 h69
  text "X" at 21930,7446.5 h69
  text "AS SHOWN" at 19291,7444.5 h69
  text "NC_ DRILL FILES" at 22126,7444.5 h69
  text "20um" at 20492,7266.5 h69
  text "X" at 20300,7265.5 h69
  text "AS SHOWN" at 21082.5,6909 h69
  text "X" at 20892.47,6908.36 h69
  text "X" at 20896,6517.5 h69
  text "X" at 21940,6517.5 h69
  text "COMPONENT" at 21082,6515.5 h69
  text "SOLDER" at 22126,6515.5 h69
  text "WHITE" at 19291,6338.5 h69
  text "X" at 19097.76,6335.66 h69
  text "SCREEN PRINT" at 21082,6142.5 h69
  text "X" at 20891.96,6138 h69
  text "BLACK" at 22099.96,5964.36 h69
  text "GLOSS" at 19291,5963 h69
  text "X" at 19100.96,5960 h69
  text "X" at 21935.96,5960 h69
  text "3um IMMERSION GOLD SMOBC (SOLDER MASK OVER BARE COPPER)" at 19291,5217.5 h69
  text "X" at 19102.05,5212.18 h69
  text "X" at 19100,4667.5 h69
  text "CUT AND TRIM ACCORDING TO LAYER MECHANICAL 1 (BOARD OUTLINE)" at 19291,4665.5 h69
  text "N.C. ROUTE" at 20256,4133 h69
  text "X" at 20065.96,4132.36 h69
  text "X" at 19101.5,3667.5 h69
  text "IN A/W ANSI IPC-A-600F" at 19290.5,3661.5 h69
  text "2" at 21378.5,3661.5 h69
  text "X" at 21227.56,3656.18 h69
  text "NONE" at 19290.5,3011.5 h69
  text "X" at 19099.29,3005.55 h69
  text "2" at 22558,2833.5 h69
  text "X" at 22367.96,2829 h69
  text "PER ORDER" at 22085.96,2661.86 h69
  text "OTHER" at 21633,2654 h69
  text "X" at 21445.75,2645.79 h69
  text "X" at 20641,2481.5 h69
  text "REQUIRED" at 20841,2478.5 h69
  text "2 SIDES" at 20963.71,2300.5 h69
  text "0.65MM" at 22329.66,2298.07 h69
  text "X" at 20769.96,2291.36 h69
  text "LEGEND" at 20964,2124.5 h69
  text "X" at 20773.96,2120 h69
  text "X" at 19930,1946.5 h69
  text "IS09001/AS3901" at 20117,1946.5 h69
  text "X" at 19628.62,1751.5 h69
  text "PER ORDER" at 19825.62,1750.5 h69
Mechanical 6:
  drawing of 642 lines, arcs and shapes, not listed
  text "DESIGN INFORMATION" at 17933,16019.36 h79
  text "PRODUCT FAMILY" at 1046.66,15989.53 h118.11
  text "DRAWING ID/MODEL." at 3940.36,15989.53 h118.11
  text "(REFER ALSO PROFILING INFORMATION)" at 20450,15870.36 h69
  text "BOARD TECHNOLOGY" at 17933,15861.36 h75
  text "BOARD SIZE" at 19764,15861.36 h75
  text "X" at 20382.96,15725.86 h69
  text "(MIN. TRACK / PADS / CLEARANCE" at 17935,15555.36 h69
  text "IN 0.001\" )" at 19706,15555.36 h69
  text "EXTERNAL" at 19987,15435.36 h69
  text "PER IPC-D-275 CLASS 2" at 20539,15435.36 h69
  text "LEVEL C AND IS THE" at 21867,15435.36 h69
  text "MINIMUM ANNULAR RING 0.05MM" at 17935,15434.36 h69
  text "(0.002\")" at 19529,15434.36 h69
  text "MANUFACTURING REGISTRATION" at 17940,15317.36 h69
  text "ALLOWANCE" at 19495,15317.36 h69
  text "CIRCUIT TYPE:" at 17933,14937.36 h75
  text "SS" at 18933.12,14937.36 h69
  text "PTH MULTILAYER" at 20491,14937.36 h69
  text "Number of Layers :" at 21555,14937.36 h69
  text "FINGER CONNECTOR DIM PER:" at 17933,14760.36 h75
  text "AS SHOWN" at 21555,14760.36 h69
  text "No. OFF TOTAL" at 18957,14602.36 h69
  text "BOTH SIDES" at 21555,14583.86 h69
  text "ONE SIDE" at 20492,14582.36 h69
  text "BUILD STATISTICS" at 12517.23,14567.75 h60
  text "BUILD STATISTICS" at 12517.23,14567.75 h60
  text "GENERAL" at 12509.23,14421.75 h40
  text "GENERAL" at 12509.23,14421.75 h40
  text "VIAS:" at 17933,14385.36 h75
  text "BURIED LAYER SEQUENCE" at 20866,14385.36 h69
  text "NONE" at 18428.35,14384.34 h69
  text ".Net_Count" at 12890.23,14338.75 h40
  text ".Net_Count" at 12890.23,14338.75 h40
  text "NETS" at 12512.23,14336.75 h35
  text "NETS" at 12512.23,14336.75 h35
  text ".Component_Count" at 12890.23,14256.75 h40
  text ".Component_Count" at 12890.23,14256.75 h40
  text "COMPONENTS" at 12513.23,14255.75 h35
  text "COMPONENTS" at 12513.23,14255.75 h35
  text "2 SIZES" at 19921,14188.36 h69
  text "BLIND LAYER SEQUENCE" at 20866,14188.36 h69
  text "PRIMITIVES" at 12510.23,14118.75 h40
  text "PRIMITIVES" at 12510.23,14118.75 h40
  text ".Fill_Count" at 12890.23,14034.75 h40
  text ".Fill_Count" at 12890.23,14034.75 h40
  text "FILLS" at 12513.23,14033.75 h35
  text "FILLS" at 12513.23,14033.75 h35
  text "LAYER CONSTRUCTION PER:" at 17933,14011.36 h75
  text "LAMINATION SEQUENCE" at 19744,14011.36 h69
  text ".Track_Count" at 12890.23,13953.75 h40
  text ".Track_Count" at 12890.23,13953.75 h40
  text "TRACKS" at 12513.23,13951.75 h35
  text "TRACKS" at 12513.23,13951.75 h35
  text ".String_Count" at 12890.23,13871.75 h40
  text ".String_Count" at 12890.23,13871.75 h40
  text "STRINGS" at 12513.23,13869.75 h35
  text "STRINGS" at 12513.23,13869.75 h35
  text "NB2.05" at 21428.47,13843.78 h70
  text "FILE NAME:" at 20881.34,13832.08 h69
  text "ARTWORK:" at 17933,13815.36 h75
  text "MANUAL" at 18932.8,13815.36 h69
  text "DIGITISED" at 19685,13815.36 h69
  text ".Arc_Count" at 12890.23,13788.75 h40
  text ".Arc_Count" at 12890.23,13788.75 h40
  text "ARC'S" at 12513.23,13786.75 h35
  text "ARC'S" at 12513.23,13786.75 h35
  text "GERBER SET" at 21428.47,13729.6 h69
  text "FILE TYPE:" at 20881.34,13727.08 h69
  text "LANDS" at 12509.23,13667.75 h40
  text "LANDS" at 12509.23,13667.75 h40
  text ".Pad_Count" at 12890.23,13583.75 h40
  text ".Pad_Count" at 12890.23,13583.75 h40
  text "PADS" at 12513.23,13581.75 h35
  text "PADS" at 12513.23,13581.75 h35
  text "SUPPLIED ARTWORK/PATTERN MASTER LIST" at 17933,13567.36 h79
  text ".Via_Count" at 12890.23,13501.75 h40
  text ".Via_Count" at 12890.23,13501.75 h40
  text "VIA'S" at 12514.23,13500.75 h35
  text "VIA'S" at 12514.23,13500.75 h35
  text "DRAWING No./CAD FILE REF." at 19786,13417.36 h69
  text "REVISION" at 22392.18,13411.87 h69
  text "DESCRIPTION" at 18150,13410.36 h69
  text "PRINT SCALE" at 12506.23,13350.75 h40
  text "PRINT SCALE" at 12506.23,13350.75 h40
  text ".Print_Scale" at 12888.23,13265.75 h40
  text ".Print_Scale" at 12888.23,13265.75 h40
  text "SCALE" at 12511.23,13264.75 h35
  text "SCALE" at 12511.23,13264.75 h35
  text "MANUFACTURE DATA" at 13932.98,12799.05 h40
  text "POLYIMIDE" at 20923.25,9542.89 h69
  text "FR4-01" at 18869.81,9540 h69
  text "FR4-04" at 19578.81,9540 h69
  text "FR4-08" at 20267.81,9540 h69
  text "ARLON" at 21664.81,9540 h69
  text "MATERIAL:" at 17934.39,9532.9 h75
  text "THICKNESS:" at 18425,9353 h69
  text "~0.8mm" at 19291,9353 h69
  text "2.2mm" at 21378,9353 h69
  text "3.2mm" at 22086,9353 h69
  text "TOLERANCE:" at 18386,9175 h69
  text "OTHER +/-" at 21614,9175 h69
  text "BOW & TWIST:" at 18268,8998 h69
  text "AS SHOWN" at 21614,8998 h69
  text "COPPER THICKNESS (FINISHED)" at 18110,8820 h69
  text "18um (1/2oz)" at 19291,8644.5 h69
  text "OUTER:" at 18622,8643 h69
  text "70um (2oz)" at 21614,8643 h69
  text "18um (1/2oz)" at 19291,8467.5 h69
  text "INNER SIGNAL:" at 18287,8466 h69
  text "70um (2oz)" at 21614,8466 h69
  text "18um (1/2oz)" at 19291,8291.5 h69
  text "INNER PWR:" at 18405,8290 h69
  text "70um (2oz)" at 21614,8290 h69
  text "STRUCTURE:" at 17953,8093 h75
  text "REFER" at 19291.16,8093 h69
  text "AS PER DRAWING No." at 19291,7916 h69
  text "DRILLING:" at 17953,7758 h75
  text "VIEWED FROM:" at 18287,7621 h69
  text "SOLDER SIDE" at 20492,7621 h69
  text "REFERENCE:" at 18386,7443 h69
  text "PATTERN MASTER LIST" at 20492,7443 h69
  text "PTH MINIMUM COPPER THICKNESS:" at 18523,7265 h69
  text "OTHER" at 21614,7265 h69
  text "NPTH:" at 18661,7087 h69
  text "TENTED" at 19291,7087 h69
  text "PADS REMOVED" at 20492,7087 h69
  text "REMOVE PADS" at 21614,7087 h69
  text "NONE" at 22121.87,6910.5 h69
  text "2nd DRILL" at 19291,6909 h69
  text "BOTH" at 20492,6909 h69
  text "ETCHING" at 19291,6693.5 h69
  text "BOARD FINISH:" at 17953,6692 h75
  text "REFER PATTERN MASTER LIST" at 20492,6692 h69
  text "LEGEND / SCREEN PRINT:" at 18523,6514 h69
  text "NONE" at 20197,6514 h69
  text "BUILD CONFIGURATION AND SPECIFICATIONS SUMMARY" at 11296.23,6362.28 h80
  text "COLOUR:" at 18523,6337 h69
  text "YELLOW" at 20492,6337 h69
  text "OTHER" at 21614,6337 h69
  text "PCB MATERIAL SPEC" at 9156.64,6283.04 h80
  text "2 Layer Build" at 11375.13,6192.78 h60
  text "Silk-Screened White Legend" at 13141.13,6192.78 h60
  text "SOLDER RESIST:" at 18209,6141 h69
  text "LIQUID PHOTOIMAGEABLE" at 19291,6141 h69
  text "5 Thou Tracks / 3 Thou Spacing" at 11375.14,6082.78 h60
  text "DO NOT TRIM Legend (Silkscreen)" at 13141.13,6082.78 h60
  text "24 Thou Via / 0.30mm Hole" at 11375.14,5972.78 h60
  text "Board Thickness Approx 1.6mm" at 13141.14,5972.8 h60
  text "MATTE" at 19879.96,5964.36 h69
  text "COLOUR:" at 18523,5963 h69
  text "BLUE" at 21082,5963 h69
  text "G/Y" at 21614,5963 h69
  text "GREEN" at 20487.26,5959.8 h69
  text "r = TYP 4.1" at 9287.98,5951.3 h100
  text "1 Oz Copper Clad" at 11375.13,5862.78 h60
  text "BOARD OUTLINE Layer Denotes Board Cutout" at 13141.13,5862.78 h60
  text "TRACK FINISH:" at 17953,5767 h75
  text "SELECTIVE SOLDER" at 19291,5767 h69
  text "REFLOW SOLDER" at 20846,5767 h69
  text "3um Immersion Gold" at 11375.13,5752.78 h60
  text "Must be BBT (Bare Board Tested)" at 13141.13,5752.78 h60
  text "Standard FR408 Style Material" at 9252.53,5682.37 h60
  text "Gloss Black Solder Mask" at 11375.13,5642.78 h60
  text "Include BBT Certificate with Order" at 13141.13,5642.78 h60
  text "HASL (HOT AIR SOLDER LEVEL)" at 19291.29,5580.26 h69
  text "Dielectric at 1GHz = TYP 4.2" at 9252.53,5572.37 h60
  text "Include All BBT Failed Boards With Order" at 11376.13,5520.78 h60
  text "FR4 Material Construction" at 9252.53,5462.37 h60
  text "REFER PATTERN MASTER LIST" at 19291,5414 h69
  text "OTHER" at 21074.76,5414 h69
  text "288'C Max. Temperature Capability" at 9252.53,5362.37 h60
  text "IPC-4101A /24 Compliant" at 9252.53,5252.37 h60
  text "Tg by DSC ('C) = 180" at 9252.53,5142.37 h60
  text "HARD GOLD PLATE FINISH" at 19291,5039 h69
  text "OTHER" at 20846,5039 h69
  text "94v0/UL94 Compliant" at 9252.53,5032.37 h60
  text "AS SHOWN" at 19291,4862 h69
  text "REFER" at 20846,4862 h69
  text "PROFILING:" at 17953,4664 h75
  text "LAYER STACK CONFIGURATION" at 12210.09,4552.07 h80
  text "REFER PCB BLANK DWG No." at 19291,4488 h69
  text "USE PROFILE/ ROUTE TAPE SUPPLIED" at 19291,4311 h69
  text "(REFER PATTERN MASTER LIST)" at 21121.26,4310.2 h69
  text "2 LAYER BUILD" at 12641.8,4270.07 h80
  text "SQUARE CUT" at 19291,4134.5 h69
  text "V. SCORE" at 21122,4133 h69
  text "BLANK" at 21929,4133 h69
  text "ACCEPTABILITY:" at 17933,3936 h75
  text "MATERIALS AND WORKMANSHIP FOR" at 19094,3936 h69
  text "ALL PRINTED WIRING BOARDS TO MEE" at 20866,3936 h69
  text "T" at 22657,3935 h69
  text "OR EXCEED THE REQUIREMENTS OF:" at 19075,3818 h69
  text "TOP LAYER" at 11765.34,3794.35 h30
  text "TL" at 12266.56,3790.85 h30
  text "-  COPPER CLAD" at 13311.33,3788.69 h30
  text "-  CORE" at 13337.09,3735.87 h30
  text "-  COPPER CLAD" at 13311.33,3681.19 h30
  text "BOTTOM LAYER" at 11766.26,3673.87 h30
  text "BL" at 12266.22,3673.87 h30
  text "1" at 21063.5,3660 h69
  text "3" at 21732.5,3660 h69
  text "UL CERTIFICATION" at 19290.5,3482 h69
  text "AUSTEL" at 21102.5,3482 h69
  text "A" at 20433.58,3305.67 h69
  text "B" at 20748.58,3305.67 h69
  text "MIL-P-55110E GRP" at 19290.5,3305 h69
  text "AS2546" at 21096.9,3305 h69
  text "OTHER" at 21889.9,3305 h69
  text "ADDITIONAL REQUIREMENTS:" at 17930,3145 h75
  text "MICROSECTION:" at 18189,3010 h69
  text "SAMPLE PLAN" at 19822.76,3010 h69
  text "MIL-P-55110E SERIAL Nos. PER ORDER" at 20846.45,3010 h69
  text "MIL-P-55110E GRP" at 19822,2832.56 h69
  text "A" at 20965.08,2833.23 h69
  text "B" at 21280.08,2833.23 h69
  text "CERTIFICATION:" at 18189,2832 h69
  text "NONE" at 19290.5,2832 h69
  text "IPC CLASS:" at 21436,2832 h69
  text "1" at 22205,2832 h69
  text "3" at 22874,2832 h69
  text "TOTAL BOARD THICKNESS: APPROX" at 12115.25,2744.87 h30
  text "1.2mm" at 12949.25,2744.86 h30
  text "(47.244mil)" at 13123.95,2745.47 h30
  text "QUALITY RELEASE REPORT" at 19822,2654 h69
  text "ELECTRICAL TEST: Bare Board" at 18189,2477 h66.93
  text "NONE" at 19822,2477 h69
  text "PER ORDER" at 21633,2477 h69
  text "MIN. PITCH" at 21634,2300.17 h69
  text "SURFACE MOUNT:" at 18189,2299 h69
  text "NONE" at 19822,2299 h69
  text "1 SIDE" at 20385.96,2296.86 h69
  text "MANUFACTURER'S ID/LOGO:" at 18189,2123 h69
  text "NONE" at 19822,2123 h69
  text "FOIL" at 20412.31,2123 h69
  text "REFER" at 21634,2123 h69
  text "NONE" at 21438,1945 h69
  text "MANUFACTURER'S ACCREDITATION:" at 18189,1925 h69
  text "PACKAGING AND HANDLING:" at 18189,1749 h69
  text "REFER" at 20841,1749 h69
